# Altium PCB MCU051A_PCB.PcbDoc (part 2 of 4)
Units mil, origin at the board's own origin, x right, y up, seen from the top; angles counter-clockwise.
Board outline 4000 x 6000 mil, 6 copper layers (Top Layer, Signal Layer 1, Signal Layer 2, Signal Layer 3, Signal Layer 4, Bottom Layer), stack 60.4 mil thick; 193 components, 239 nets, 864 pads, 621 vias.
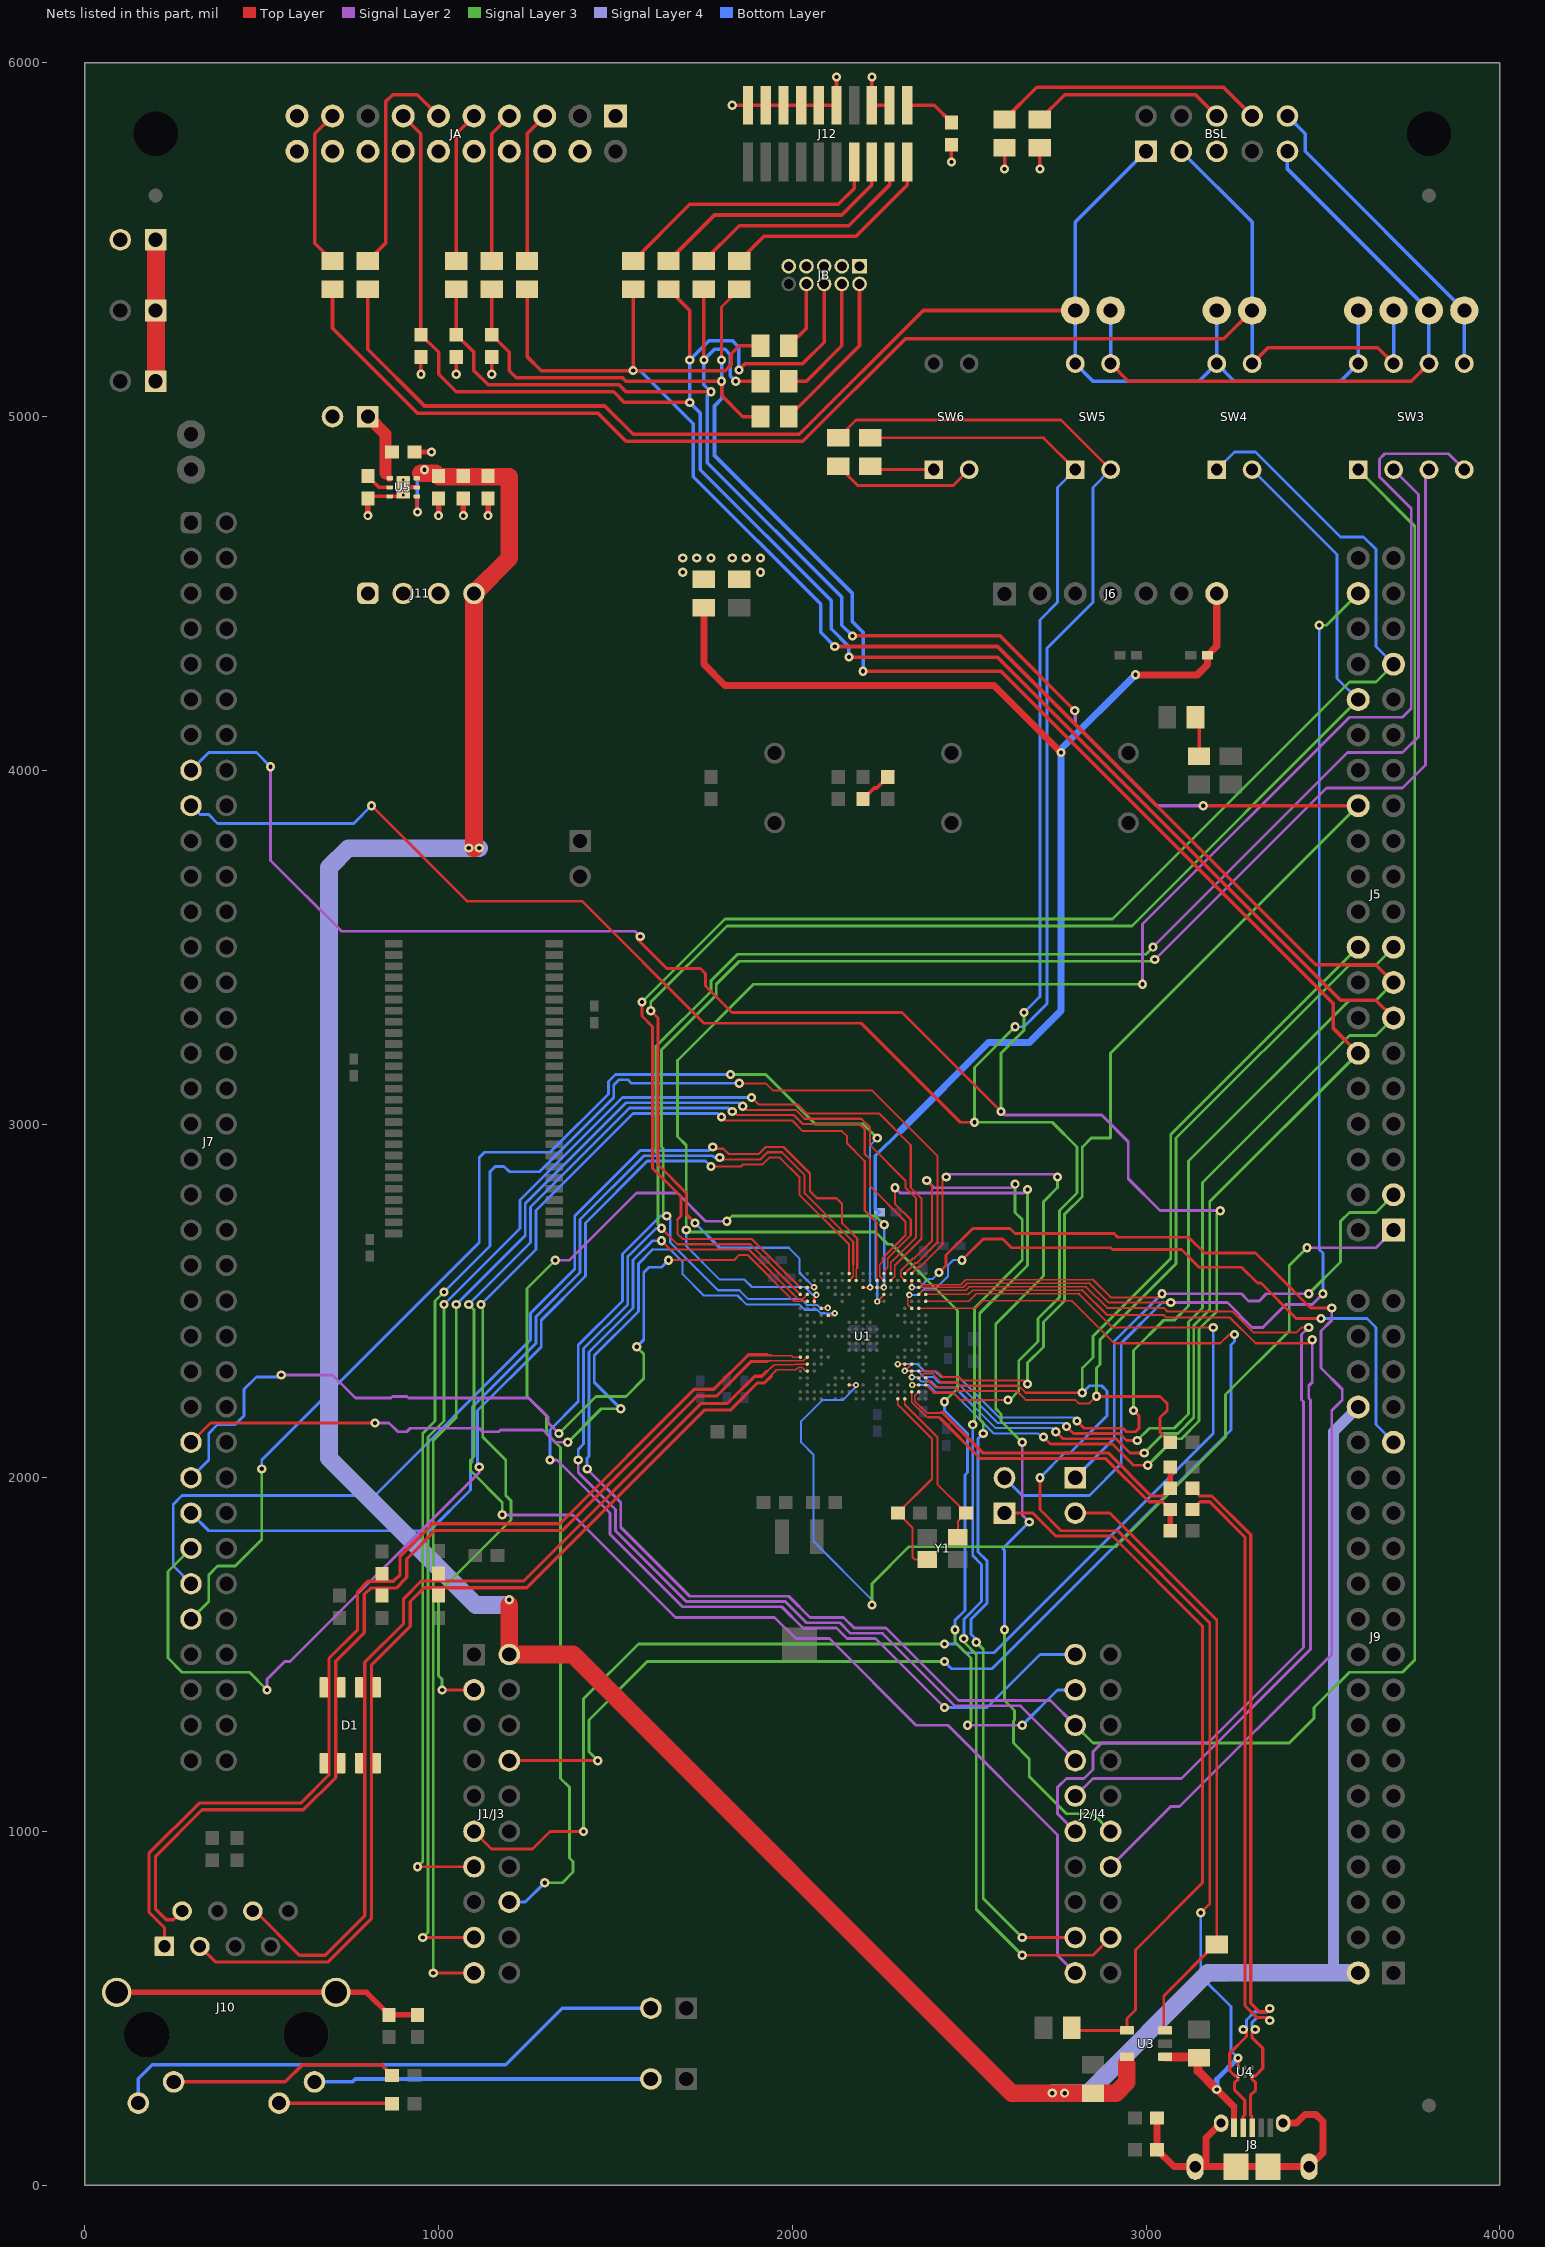
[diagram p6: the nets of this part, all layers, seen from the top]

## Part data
BSL: library part CMP-0075161-1, "Header(Shrouded), 2.54mm, 5x2, Gold, TH", Color=Gray, Manufacturer="Assman WSW", Supplier Part Number 1=AWHW-10G-0202-T-ND
C1 C2 C3 C14 C15 C16 C17 C19 C20 C21 C22 C23 C24 C25 C26 C30 C34: library part CMP-0006629-2, "CAP, CERM, 0.1 uF, 10 V, +/- 10%, X7R, 0402", Cap_Case=0402, Manufacturer=MuRata, Supplier Part Number 1=GRM155R71A104KA01D-ND, TempCo=X7R, Tolerance_%=10%, Value1=Unknown, Value2=10V, ValueDisplayed=0.1uF
C4 C8 C9 C12 C13 C36: library part CMP-0007378-5, "CAP, CERM, 0.1 uF, 16 V, +/- 10%, X7R, 0603", Cap_Case=0603, Manufacturer=MuRata, Supplier Part Number 1=490-1532-1-ND, TempCo=X7R, Tolerance_%=10%, Value1=Unknown, Value2=16V, ValueDisplayed=0.1uF
C5: library part CMP-0007724-2, "CAP, CERM, 0.1 uF, 16 V, +/- 10%, X7R, 0805", Cap_Case=0805, Manufacturer=Kemet, Supplier Part Number 1=399-1167-1-ND, TempCo=X7R, Tolerance_%=10%, Value1="0.064 ohm", Value2=16V, ValueDisplayed=0.1uF
C6 C7 C10 C11: library part CMP-0007178-4, "CAP, CERM, 12 pF, 50 V, +/- 5%, C0G/NP0, 0603", Cap_Case=0603, Manufacturer=MuRata, Supplier Part Number 1=490-1405-1-ND, TempCo=C0G/NP0, Tolerance_%=5%, Value1=Unknown, Value2=50V, ValueDisplayed=12pF
C18: library part CMP-0006746-5, "CAP, CERM, 4700 pF, 100 V, +/- 10%, X7R, 0603", Cap_Case=0603, Manufacturer=AVX, Supplier Part Number 1=478-1203-1-ND, TempCo=X7R, Tolerance_%=10%, Value1="0.136 ohm", Value2=100V, ValueDisplayed=4700pF
C27 C28: library part CMP-0007690-2, "CAP, CERM, 4.7 uF, 10 V, +/- 10%, X7R, 0805", Cap_Case=0805, Manufacturer="Wurth Elektronik", Supplier Part Number 1=710-885012207025, TempCo=X7R, Tolerance_%=10%, Value1=Unknown, Value2=10V, ValueDisplayed=4.7uF
C29 C33: library part CMP-0064947-2, "CAP, CERM, 1 uF, 6.3 V,+/- 10%, X7R, 0402", Cap_Case=0402, Manufacturer=MuRata, Supplier Part Number 1=490-10024-1-ND, TempCo=X7R, Tolerance_%=10%, Value1=Unknown, Value2=6.3V, ValueDisplayed=1uF
C31: library part CMP-0007445-4, "CAP, CERM, 0.22 uF, 50 V, +/- 10%, X7R, 0603", Cap_Case=0603, Manufacturer=MuRata, Supplier Part Number 1=490-12546-1-ND, TempCo=X7R, Tolerance_%=10%, Value1=Unknown, Value2=50V, ValueDisplayed=0.22uF
C32 C38: library part CMP-0007499-4, "CAP, CERM, 2.2 uF, 16 V, +/- 10%, X7R, 0603", Cap_Case=0603, Manufacturer=MuRata, Supplier Part Number 1=81-GRM188Z71C225KE3D, TempCo=X7R, Tolerance_%=10%, Value1=Unknown, Value2=16V, ValueDisplayed=2.2uF
C35: library part CMP-0007365-4, "CAP, CERM, 1 uF, 10 V, +/- 10%, X7R, 0603", Cap_Case=0603, Manufacturer=MuRata, Supplier Part Number 1=490-3899-1-ND, TempCo=X7R, Tolerance_%=10%, Value1="0.011 ohm", Value2=10V, ValueDisplayed=1uF
C37 C39: library part CMP-0007377-4, "CAP, CERM, 0.01 uF, 16 V, +/- 10%, X7R, 0603", Cap_Case=0603, Manufacturer=MuRata, Supplier Part Number 1=490-1525-1-ND, TempCo=X7R, Tolerance_%=10%, Value1=Unknown, Value2=16V, ValueDisplayed=0.01uF
D1: library part CMP-0082307-1, "Low Capacitance TVS Array, 2.8V, SOIC-8", Manufacturer=Bourns, Supplier Part Number 1=CDNBS08-SLVU2.8-4CT-ND
FID1 FID2 FID3 FID4 FID5 FID6: library part CMP-0077181-1, "Fiducial mark.  There is nothing to buy or mount.", Manufacturer=N/A
H1 H2: library part CMP-0003658-1, Manufacturer=Keystone, Supplier Part Number 1=36-1902B-ND
J1/J3: library part CMP-0003837-2, "Receptacle, 2.54mm, 10x2, Tin, TH", Alternate Manufacturer="Major League Electronics", Alternate PartNumber=CRD-081413-A-G, Manufacturer=Samtec, Supplier Part Number 1=SAM1204-10-ND
J2/J4: library part CMP-0078266-2, "Receptacle, 2.54mm, 10x2, Tin, TH", Alternate Manufacturer="Major League Electronics", Alternate PartNumber=CRD-081413-A-G, Manufacturer=Samtec, Supplier Part Number 1=SAM1204-10-ND
J5 J9: library part CMP-0075433-1, "Header, 100mil, 20x2, Gold, TH", Color=Black, Current_A=6.3A, Manufacturer=Samtec, Supplier Part Number 1=SAM1028-20-ND, Voltage_V=550V
J6: library part CMP-0075416-1, "Header, 100mil, 7x1, Gold, TH", Color=Black, Current_A=6.3A, Manufacturer=Samtec, Supplier Part Number 1=SAM1029-07-ND, Voltage_V=550V
J7: library part CMP-0080465-1, "Header, 2.54mm, 36x2, Gold, TH", Color=Black, Manufacturer=Samtec, Supplier Part Number 1=SAM1028-36-ND
J8: library part CMP-0075082-1, "Connector, Receptacle, Micro-USB Type AB, R/A, Bottom Mount SMT", Manufacturer="Hirose Electric Co. Ltd.", Supplier Part Number 1=H11494CT-ND
J10: library part CMP-0055856-1, "Connector, RJ45 with integrated magnetics, 1x1, Gold, R/A, TH", Manufacturer="Pulse Engineering", Supplier Part Number 1=553-1485-ND
J11: library part CMP-0078238-2, "Header, 2.54mm, 4x1, Tin, TH", Color=Black, Manufacturer=Samtec, Supplier Part Number 1=SAM1035-04-ND
J12: library part CMP-0075631-1, "Header (Shrouded), 1.27mm, 10x2, Tin, SMT", Color=Black, Current_A=3.3A, Manufacturer=Samtec, Supplier Part Number 1=SAM8803-ND
JA: library part CMP-0054842-1, "Header (shrouded), 100mil, 10x2,  Gold, TH", Manufacturer="TE Connectivity", Supplier Part Number 1=A33166-ND
JB: library part CMP-0075533-1, "Header, 1.27 mm, 5x2, Gold, TH", Color=Black, Manufacturer=Samtec, Supplier Part Number 1=FTSH-105-01-F-D-K-ND
JP1 JP2 JP3 JP4 JP5 JP6 JP7 JP8 JP9: library part CMP-0075500-1, "Header, 100mil, 2x1, Gold, TH", Manufacturer=Samtec, Supplier Part Number 1=HMTSW-102-07-G-S-240-ND
Logo1: library part CMP-0074838-1, "Texas Instrument Corporate Signature"
Logo2: library part CMP-0074844-1
Logo3: library part CMP-0074847-1, "FCC_disclaimer"
Logo4: library part CMP-0074769-1
MH1 MH2: library part CMP-0078424-2, "PCB Mounting Hole, No Pad", Manufacturer=Any, PartNumber=N/A
R1: library part CMP-0025925-3, "RES, 47 k, 5%, 0.1 W, 0603", Manufacturer="Yageo America", Power_W=100mW, Supplier Part Number 1=311-47KGRCT-ND, TempCo="100 ppm/C", Tolerance_%=5%, Value2=0.1W, Value_Code=47k0, ValueDisplayed=47k
R2: library part CMP-0025825-4, "RES, 51, 5%, 0.1 W, AEC-Q200 Grade 0, 0603", Manufacturer=Vishay-Dale, Power_W=100mW, Supplier Part Number 1=541-51GCT-ND, TempCo="200 ppm/C", Tolerance_%=5%, Value2=0.1W, Value_Code=51R0, ValueDisplayed=51
R3: library part CMP-0020445-3, "RES, 100, 5%, 0.125 W, AEC-Q200 Grade 0, 0805", Manufacturer=Vishay-Dale, Power_W=125mW, Supplier Part Number 1=541-100ACT-ND, TempCo="200 ppm/C", Tolerance_%=5%, Value2=0.125W, Value_Code=100R, ValueDisplayed=100
R4 R32 R33: library part CMP-0020446-3, "RES, 10 k, 5%, 0.125 W, AEC-Q200 Grade 0, 0805", Manufacturer=Vishay-Dale, Power_W=125mW, Supplier Part Number 1=541-10KACT-ND, TempCo="200 ppm/C", Tolerance_%=5%, Value2=0.125W, Value_Code=10k0, ValueDisplayed=10k
R5 R14: library part CMP-0025736-4, "RES, 1.0 M, 5%, 0.1 W, AEC-Q200 Grade 0, 0603", Manufacturer=Vishay-Dale, Power_W=100mW, Supplier Part Number 1=541-1.0MGCT-ND, TempCo="200 ppm/C", Tolerance_%=5%, Value2=0.1W, Value_Code=1M00, ValueDisplayed=1.0M
R6: library part CMP-0023154-3, "RES, 4.87 k, 1%, 0.1 W, 0603", Manufacturer="Yageo America", Power_W=100mW, Supplier Part Number 1=311-4.87KHRCT-ND, TempCo="200 ppm/C", Tolerance_%=1%, Value2=0.1W, Value_Code=4k87, ValueDisplayed=4.87k
R7 R15 R24 R25: library part CMP-0020803-2, "RES, 0, 5%, 0.125 W, 0805", Manufacturer="Yageo America", Power_W=125mW, Supplier Part Number 1=311-0.0ARCT-ND, TempCo="200 ppm/C", Tolerance_%=5%, Value2=0.125W, Value_Code=0000, ValueDisplayed=0
R8 R9 R12 R13: library part CMP-0023143-3, "RES, 49.9, 1%, 0.1 W, 0603", Manufacturer="Yageo America", Power_W=100mW, Supplier Part Number 1=311-49.9HRCT-ND, TempCo="200 ppm/C", Tolerance_%=1%, Value2=0.1W, Value_Code=49R9, ValueDisplayed=49.9
R10 R11: library part CMP-0020559-3, "RES, 4.7 k, 5%, 0.125 W, AEC-Q200 Grade 0, 0805", Manufacturer=Vishay-Dale, Power_W=125mW, Supplier Part Number 1=541-4.7KACT-ND, TempCo="200 ppm/C", Tolerance_%=5%, Value2=0.125W, Value_Code=4k70, ValueDisplayed=4.7k
R16 R23: library part CMP-0025912-3, "RES, 330, 5%, 0.1 W, 0603", Manufacturer="Yageo America", Power_W=100mW, Supplier Part Number 1=311-330GRCT-ND, TempCo="100 ppm/C", Tolerance_%=5%, Value2=0.1W, Value_Code=330R, ValueDisplayed=330
R17 R18 R19 R20 R21 R22 R34 R38 R40 R41: library part CMP-0020509-3, "RES, 27, 5%, 0.125 W, AEC-Q200 Grade 0, 0805", Manufacturer=Vishay-Dale, Power_W=125mW, Supplier Part Number 1=541-27ACT-ND, TempCo="200 ppm/C", Tolerance_%=5%, Value2=0.125W, Value_Code=27R0, ValueDisplayed=27
R26 R27 R28 R29: library part CMP-0025697-4, "RES, 0, 5%, 0.1 W, AEC-Q200 Grade 0, 0603", Manufacturer=Vishay-Dale, Power_W=100mW, Supplier Part Number 1=541-0.0GCT-ND, TempCo="200 ppm/C", Tolerance_%=5%, Value2=0.1W, Value_Code=0000, ValueDisplayed=0
R30: library part CMP-0025700-4, "RES, 100, 5%, 0.1 W, AEC-Q200 Grade 0, 0603", Manufacturer=Vishay-Dale, Power_W=100mW, Supplier Part Number 1=541-100GCT-ND, TempCo="200 ppm/C", Tolerance_%=5%, Value2=0.1W, Value_Code=100R, ValueDisplayed=100
R31: library part CMP-0025913-3, "RES, 33 k, 5%, 0.1 W, 0603", Manufacturer="Yageo America", Power_W=100mW, Supplier Part Number 1=311-33KGRCT-ND, TempCo="100 ppm/C", Tolerance_%=5%, Value2=0.1W, Value_Code=33k0, ValueDisplayed=33k
R35 R36 R37: library part CMP-0025945-3, "RES, 10 k, 5%, 0.1 W, 0603", Manufacturer="Samsung Electro-Mechanics", Power_W=100mW, Supplier Part Number 1=1276-5086-1-ND, TempCo="100 ppm/C", Tolerance_%=5%, Value2=0.1W, Value_Code=10k0, ValueDisplayed=10k
R39: library part CMP-0022736-2, "RES, 100, 1%, 0.1 W, 0603", Manufacturer="Yageo America", Power_W=100mW, Supplier Part Number 1=311-100HRCT-ND, TempCo="200 ppm/C", Tolerance_%=1%, Value2=0.1W, Value_Code=100R, ValueDisplayed=100
R42 R43: library part CMP-0020442-3, "RES, 0, 5%, 0.125 W, AEC-Q200 Grade 0, 0805", Manufacturer=Vishay-Dale, Power_W=125mW, Supplier Part Number 1=541-0.0ACT-ND, TempCo="200 ppm/C", Tolerance_%=5%, Value2=0.125W, Value_Code=0000, ValueDisplayed=0
SH-J7-1 SH-J7-2 SH-J7-3 SH-J7-4 SH-J7-5 SH-J7-6 SH-J7-7 SH-J7-8 SH-J7-9 SH-J7-10 SH-J7-11 SH-J7-12 SH-J7-13 SH-J7-14 SH-J7-15 SH-J7-16 SH-J7-17 SH-J7-18 SH-J7-19 SH-J7-20 SH-J7-21 SH-J7-22 SH-J7-23 SH-J7-24 SH-J7-25 SH-J7-26 SH-J7-27 SH-J7-28 SH-J7-29 SH-J7-30 SH-J7-31 SH-J7-32 SH-J7-33 SH-J7-34 SH-J7-35 SH-J7-36 SH-JP1 SH-JP2 SH-JP3 SH-JP4 SH-JP5 SH-JP6 SH-JP7 SH-JP8 SH-JP9: library part CMP-0003623-1, "Shunt, 100mil, Gold plated, Black", Alternate Manufacturer=3M, Alternate PartNumber=969102-0000-DA, Manufacturer=Samtec, Supplier Part Number 1=SNT-100-BK-G-ND
SW1 SW2 SW7: library part CMP-0074594-1, "Switch, SPST-NO, Off-Mom, 0.02 A, 15 VDC, TH", CurrentRating_mA=20A, Manufacturer=Panasonic, Supplier Part Number 1=P8070SCT-ND
SW3: library part CMP-0002271-1, "Switch, 4PST, Slide, Off-On, 1 Pos, 0.15A, 30V, TH", CurrentRating_mA=150A, Manufacturer=Grayhill, Supplier Part Number 1=GH7198-ND
SW4 SW5 SW6: library part CMP-0002270-1, "Switch, DPST, Slide, Off-On, 1 Pos, 0.15A, 30V, TH", CurrentRating_mA=150A, Manufacturer=Grayhill, Supplier Part Number 1=GH7727-ND
TP1 TP2 TP3 TP4 TP5 TP6 TP7 TP8 TP9 TP10: library part CMP-0055138-1, "Test Point, Miniature, Black, TH", Color=Black, Manufacturer=Keystone, Supplier Part Number 1=36-5001-ND
U1: library part CMP-0077957-1, "MSP432E411YTZAD, ZAD0212A (NFBGA-212)", Alternate Manufacturer="Texas Instruments", Alternate PartNumber=MSP432E411YTZADR
U2: library part CMP-0004972-1, "32Mx16 512Mb SDRAM, TSOP-2_54", Manufacturer="Integrated Silicon Solution Inc.", Supplier Part Number 1=706-1450-5-ND
U3: library part CMP-0074276-1, "Single, Current-Limited, Power-Distribution Switch, DBV0005A (SOT-23-5)", Alternate Manufacturer="Texas Instruments", Alternate PartNumber=TPS2051BDBVT
U4: library part CMP-0043122-2, "USB ESD Solution with Power Clamp, 4 Channels, -40 to +85 degC, 6-pin SON (DRY), Green (RoHS & no Sb/Br)", Breakdown Voltage(Min)(V)=6, IO Capacitance(Typ)(pF)=0.8, IO Leakage Current(nA)=10, Manufacturer="Texas Instruments"
U5: library part CMP-0036330-5, "Single Output High PSRR LDO, 500 mA, Fixed 3.3 V Output, 2.7 to 6.5 V Input, with Low IQ, 6-pin SON (DRV), -40 to 125 degC, Green (RoHS & no Sb/Br)", Manufacturer="Texas Instruments"
Y1: library part CMP-0004652-3, "Crystal, 25 MHz, 8pF, SMD", Frequency_Fixed=25MHz, Frequency Stability=+/-20ppm, Manufacturer=Fox, Supplier Part Number 1=631-1478-1-ND
Y2: library part CMP-0004653-5, "Crystal, 32.768 kHz,  SMD", Frequency_Fixed=32.768kHz, Frequency Stability=+/-20ppm, Manufacturer="Citizen FineDevice", Supplier Part Number 1=695-CMR200T32.7KY-U
ZZ2: library part CMP-0077236-1
ZZ3: library part CMP-0077237-1
ZZ4 ZZ5 ZZ6: library part CMP-0077238-1

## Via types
v1: diameter 26, hole 12, Top Layer to Bottom Layer, tented both sides, 517 vias
v2: diameter 18, hole 8, Top Layer to Bottom Layer, tented both sides, 94 vias
v3: diameter 26, hole 12, Top Layer to Bottom Layer, 7 vias
v4: diameter 19.68, hole 7.87, Top Layer to Bottom Layer, 2 vias
v5: diameter 18, hole 8, Top Layer to Bottom Layer, 1 vias

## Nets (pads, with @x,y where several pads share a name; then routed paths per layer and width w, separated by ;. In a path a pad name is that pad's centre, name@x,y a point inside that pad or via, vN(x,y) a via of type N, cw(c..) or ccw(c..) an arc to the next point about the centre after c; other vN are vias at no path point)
3V3: J11.1 JA.1 JA.19 JB.1 JP1.2 JP8.2 R7.1 R15.1 R35.1 R36.1 R37.1 R39.1 | length 314
  Top Layer w10: v1(950,5120) R37.1@950,5168.5 ; v1(1050,5120) R36.1@1050,5168.5 ; v1(1150,5120) R35.1@1150,5168.5 ; v1(2450,5720) R39.1@2450,5768.5 ; v1(2600,5700) R7.1@2600,5760 ; v1(2700,5700) R15.1@2700,5760
5V0: C28.1 C35.1 C36.1 C37.1 J1/J3.21 J9.2 J9.34 J11.4 U3.5 U5.4 U5.6 | length 9432.4
  Top Layer w10: U5.4@938.39,4774.41 938.39,4731.61 v1(940,4730)
  Top Layer w25: 2945.87,342.5 U3.5@2945.87,362.6
  Top Layer w50: 950,4840 991.5,4840 C37.1@1000,4831.5 1001.5,4830 1200,4830 1200,4600 J11.4@1100,4500 1100,3780 ; 1200,1640 J1/J3.21@1200,1500 1380,1500 2620,260 v1(2735,260) C28.1@2850,260 2915,260 2945.87,290.87 2945.87,342.5
  Signal Layer 4 w30: 3530,600 3530,2130 J9.34@3600,2200
  Signal Layer 4 w50: v1(1115,3780) 745,3780 690,3725 690,2055 1105,1640 1195,1640 ; v1(2735,260) 2835,260 3175,600 3530,600 J9.2@3600,600
  Bottom Layer w10: v1(940,4730) 940,4830 v1(960,4850)
  other v1: 2770,260 1200,1655 1085,3780
AVSS: C29.1 C30.1 J6.7 R43.2 U1.G4 | length 3884.4
  Top Layer w6: v2(2240,2498) 2259.06,2517.06 U1.G4@2259.06,2518.11
  Top Layer w20: R43.2@1750,4460 1750,4300 1810,4240 2570,4240 v1(2760,4050) ; v1(2970,4270) 3030,4270 3145,4270 3173.62,4298.62 C29.1@3173.62,4325 3200,4351.38 J6.7@3200,4500
  Bottom Layer w6: v2(2240,2498) 2240,2560.54 2235.27,2565.27 2235.27,2738.89 C30.1@2246.38,2750
  Bottom Layer w10: C30.1@2246.38,2750 2235,2761.38 2235,2910 2305,2980
  Bottom Layer w20: 2305,2980 2555,3230 2670,3230 2760,3320 v1(2760,4050) 2760,4060 v1(2970,4270)
BSLCLK: BSL.9 SW3.6 SW5.4 TP6.1 TP9.1 | length 1857.1
  Top Layer w10: SW5.4@2900,5150 2950,5100 3750,5100 SW3.6@3800,5150
  Bottom Layer w10: SW5.4@2900,5150 TP6.1@2900,5300 ; BSL.9@3400,5750 3400,5700 TP9.1@3800,5300 SW3.6@3800,5150
BSLRX: BSL.3 R25.2 SW3.4 SW4.4 TP4.1 TP8.1 | length 4265.8
  Top Layer w10: R25.2@700,5360 700,5250 940,5010 1450,5010 1530,4930 2030,4930 2320,5220 3220,5220 TP4.1@3300,5300 ; SW4.4@3300,5150 3344.88,5194.88 3655.12,5194.88 SW3.4@3700,5150
  Bottom Layer w10: BSL.3@3100,5750 3300,5550 TP4.1@3300,5300 SW4.4@3300,5150 ; SW3.4@3700,5150 TP8.1@3700,5300
BSLSDA: BSL.1 R24.2 SW3.2 SW4.2 SW5.2 TP3.1 TP5.1 TP7.1 | length 4280.1
  Top Layer w10: R24.2@800,5360 800,5190 960,5030 1470,5030 1550,4950 2020,4950 2370,5300 TP5.1@2800,5300
  Bottom Layer w10: BSL.1@3000,5750 2800,5550 TP5.1@2800,5300 SW5.2@2800,5150 2850,5100 3150,5100 SW4.2@3200,5150 ; TP3.1@3200,5300 SW4.2@3200,5150 ; TP7.1@3600,5300 SW3.2@3600,5150 3550,5100 3250,5100 SW4.2@3200,5150
BSLSTE: BSL.10 SW3.8 TP10.1 | length 907.1
  Bottom Layer w10: BSL.10@3400,5850 3450,5800 3450,5750 TP10.1@3900,5300 SW3.8@3900,5150
D_N: R26.2 R27.1 U1.B18 | length 933.3
  Top Layer w4: U1.B18@2357.48,2242.52 2346.56,2231.6 2346.56,2216.44 2380,2183 2385,2183
  Top Layer w6: 2385,2183 2419,2183 2420,2184
  Top Layer w8: 2420,2184 2425.63,2184
  Top Layer w9: 2425.63,2183 2538.63,2070 2893,2070 3015,1948 3046.5,1948 R27.1@3068.5,1970
  Top Layer w15: R27.1@3068.5,1970 R26.2@3068.5,2030
D_P: R28.2 R29.1 U1.C18 | length 945.8
  Top Layer w4: U1.C18@2337.8,2242.52 2337.8,2212.93 2379.73,2171 2385.69,2171
  Top Layer w6: 2385.69,2171 2415,2171 2418,2168
  Top Layer w9: 2418,2168 2532,2054 2886.37,2054 3008.37,1932 3046.5,1932 R29.1@3068.5,1910
  Top Layer w15: R28.2@3068.5,1850 R29.1@3068.5,1910
EN0RXI_N: D1.2 D1.7 J10.6 R12.1 U1.V14 | length 2775.2
  Top Layer w4: 1940.69,2311.9 1942.1,2311.9 1948.83,2318.63 2004.65,2318.63 2007.28,2321.26 U1.V14@2042.52,2321.26 U1.V14@2040.52,2319.26
  Top Layer w6: 1927.27,2300.61 1929.39,2300.61 1940.69,2311.9
  Top Layer w9: J10.6@475,774.8 481.47,774.8 606.28,650 680,650 791,761 791,1477.87 901,1587.87 901,1657.87 951.13,1708 1241.13,1708 1743.13,2210 1816.81,2210 1893.48,2286.67 1913.33,2286.67 1927.27,2300.61
EN0RXI_P: D1.1 D1.8 J10.3 R13.1 U1.V15 | length 2901.3
  Top Layer w4: 1952,2300.59 1952,2302 1954.63,2304.63 2010.44,2304.63 2018.31,2312.5 2027.36,2312.5 2033.76,2306.1 2033.76,2303.42 2035.6,2301.57 U1.V15@2042.52,2301.57
  Top Layer w6: 1940.71,2287.17 1940.71,2289.29 1952,2300.59
  Top Layer w9: J10.3@325,674.8 368.8,631 687.87,631 810,753.13 810,1470 920,1580 920,1650 959,1689 1249,1689 1751,2191 1824.68,2191 1901.35,2267.67 1921.2,2267.67 1940.71,2287.17
EN0TXO_N: D1.3 D1.6 J10.2 R9.1 U1.V13 | length 2962
  Top Layer w4: 1939,2330.32 1940,2331.32 1992.04,2331.32 1993.33,2330.02 2031.6,2330.02 U1.V13@2042.52,2340.94
  Top Layer w6: 1928.5,2328.82 1930,2330.32 1939,2330.32
  Top Layer w9: J10.2@275,774.8 250.2,750 230,750 200,780 200,930 331,1061 617.87,1061 709,1152.13 709,1481.13 790,1562.13 790,1670 808,1688 879.87,1688 910,1718.13 910,1770 991,1851 1351,1851 1731,2231 1786.16,2231 1883.97,2328.82 1928.5,2328.82
EN0TXO_P: D1.4 D1.5 J10.1 R8.1 U1.W13 | length 2996.2
  Top Layer w4: 1939,2346.32 1940,2345.32 1997.84,2345.32 2001.94,2341.21 ; 2001.94,2340.94 U1.W13@2022.83,2340.94
  Top Layer w6: 1928.5,2347.82 1930,2346.32 1939,2346.32
  Top Layer w9: J10.1@225,674.8 225,728.13 181,772.13 181,937.87 323.13,1080 610,1080 690,1160 690,1489 771,1570 771,1677.87 800.13,1707 872,1707 891,1726 891,1777.87 983.13,1870 1343.13,1870 1723.13,2250 1778.29,2250 1876.1,2347.82 1928.5,2347.82
GND: BSL.5 C35.2 C36.2 C37.2 C38.2 C39.2 J11.2 J11.3 J12.3 J12.5 J12.9 J12.11 J12.13 J12.15 J12.17 J12.19 JA.4 JA.6 JA.8 JA.10 JA.12 JA.14 JA.16 JA.18 JA.20 JB.3 JB.5 JB.7 JB.9 R42.1 R43.1 U5.3 U5.5 U5.7@900,4800 | length 863.9
  Top Layer w10: C39.2@805.91,4774.41 U5.3@861.61,4774.41 U5.7@884.25,4774.41 ; v3(1830.12,5880.12) J12.19@1875,5880.12 J12.17@1925,5880.12 J12.15@1975,5880.12 J12.13@2025,5880.12 J12.11@2075,5880.12 J12.9@2125,5880.12 v3(2125,5960) ; v3(2225,5960) J12.5@2225,5880.12 J12.3@2275,5880.12
  Top Layer w12: U5.7@900,4800 U5.5@938.39,4800
  Top Layer w15: v1(800,4720) C39.2@800,4768.5 ; C38.2@931.5,4900 v1(980,4900) ; v1(1000,4720) C37.2@1000,4768.5 ; v1(1070,4720) C36.2@1070,4768.5 ; v1(1140,4720) C35.2@1140,4768.5
  other v1: 1690,4560 1910,4560 1690,4600 1730,4600 1770,4600 1830,4600 1870,4600 1910,4600
  other v4: 900,4778.35 900,4821.65
HIBn: J5.1 U1.M17 | length 2950.1
  Top Layer w6: U1.M17@2160.63,2262.2 v2@2179.8,2262.2
  Signal Layer 2 w8: v1(3455,2650) 3650,2650 J5.1@3700,2700
  Signal Layer 3 w8: v1(2225,1640) 2225,1700 2330,1805 2915,1805 3225,2115 3225,2235 3405,2415 3405,2600 v1(3455,2650)
  Bottom Layer w6: v2(2180,2262) 2180,2257 2142.25,2219.25 2084.25,2219.25 2025,2160 2025,2100 2060,2065 2060,1820 2225,1655 v1(2225,1640)
NetBSL_6: BSL.6 R15.2 | length 553.8
  Top Layer w10: R15.2@2700,5840 2770,5910 3140,5910 BSL.6@3200,5850
NetBSL_8: BSL.8 R7.2 | length 771.2
  Top Layer w10: R7.2@2600,5840 2690.91,5930.91 3219.09,5930.91 BSL.8@3300,5850
NetC5_2: C5.2 R3.2 | length 114.1
  Top Layer w10: C5.2@3140,4150 3150,4140 R3.2@3150,4040
NetC18_1: C18.1 J10.13 J10.14 R14.2 | length 876.3
  Top Layer w15: J10.13@89.96,544.88 J10.14@710.04,544.88 796.61,544.88 C18.1@860,481.5 R14.2@940,481.5
NetC31_1: C31.1 J8.6 J8.7 J8.8 J8.9 J8.10 J8.11 R31.2 | length 954.8
  Top Layer w20: R31.2@3031.5,190 C31.1@3031.5,100 3079.33,52.17 J8.8@3139.07,52.17 3170,52.17 ; J8.10@3212.4,175.2 3170,132.8 3170,52.17 ; J8.11@3387.6,175.2 3425.2,175.2 3450,200 3480,200 3500,180 3500,91.24 J8.9@3460.93,52.17 J8.7@3345.28,52.17 J8.6@3254.72,52.17 3170,52.17
NetC38_1: C38.1 JP8.1 U5.1 | length 183.5
  Top Layer w20: U5.1@861.61,4825.59 U5.1@861.61,4828.39
  Top Layer w35: JP8.1@800,5000 850,4950 850,4840
NetC39_1: C39.1 U5.2 | length 74.7
  Top Layer w10: C39.1@800,4831.5 831.5,4800 U5.2@861.61,4800
NetJ10_9: J10.9 JP6.2 | length 1600.5
  Bottom Layer w10: J10.9@150.98,231.89 150.98,300.98 190,340 1190,340 1350,500 JP6.2@1600,500
NetJ10_10: J10.10 R16.2 | length 649.9
  Top Layer w10: J10.10@250.98,291.73 566.73,291.73 615,340 838.5,340 R16.2@868.5,310
NetJ10_11: J10.11 R23.2 | length 320.3
  Top Layer w10: J10.11@549.02,231.89 866.61,231.89 R23.2@868.5,230
NetJ10_12: J10.12 JP7.2 | length 954.4
  Bottom Layer w10: J10.12@649.02,291.73 756.73,291.73 765,300 JP7.2@1600,300
NetJ12_1: J12.1 R39.2 | length 145.1
  Top Layer w10: J12.1@2325,5880.12 2401.38,5880.12 R39.2@2450,5831.5
NetJ12_2: J12.2 R34.1 | length 628.9
  Top Layer w10: R34.1@1850,5440 1920,5510 2180,5510 2325,5655 J12.2@2325,5719.88
NetJ12_4: J12.4 R38.1 | length 678.9
  Top Layer w10: R38.1@1750,5440 1850,5540 2160,5540 2275,5655 J12.4@2275,5719.88
NetJ12_6: J12.6 R40.1 | length 728.9
  Top Layer w10: R40.1@1650,5440 1780,5570 2140,5570 2225,5655 J12.6@2225,5719.88
NetJ12_8: J12.8 R41.1 | length 784.8
  Top Layer w10: R41.1@1550,5440 1710,5600 2130,5600 2175,5645 J12.8@2175,5719.88
NetJA_5: JA.5 R19.1 | length 430.7
  Top Layer w10: R19.1@1250,5440 1250,5800 JA.5@1300,5850
NetJA_7: JA.7 R18.1 | length 430.7
  Top Layer w10: R18.1@1150,5440 1150,5800 JA.7@1200,5850
NetJA_9: JA.9 R17.1 | length 430.7
  Top Layer w10: R17.1@1050,5440 1050,5800 JA.9@1100,5850
NetJA_11: JA.11 R24.1 | length 653.8
  Top Layer w10: R24.1@800,5440 850,5490 850,5890 870,5910 940,5910 JA.11@1000,5850
NetJA_17: JA.17 R25.1 | length 451.4
  Top Layer w10: R25.1@700,5440 650,5490 650,5800 JA.17@700,5850
NetJB_2: JB.2 R21.2 | length 457.8
  Top Layer w10: R21.2@1990,5000 2190,5200 JB.2@2190,5375
NetJB_4: JB.4 R20.2 | length 366.4
  Top Layer w10: R20.2@1990,5100 2040,5100 2140,5200 JB.4@2140,5375
NetJB_8: JB.8 R22.2 | length 195.7
  Top Layer w10: R22.2@1990,5200 2040,5250 JB.8@2040,5375
NetJP1_1: JP1.1 JP2.1 JP3.1 | length 393
  Top Layer w50: JP2.1@201,5101 JP1.1@201,5494
NetJP4_1: JP4.1 R33.2 U3.4 | length 2067.1
  Top Layer w8: JP4.1@2600,1900 2680,1900 2745,1835 2905,1835 3160,1580 3160,855 2970,665 2970,495 2945.87,470.87 U3.4@2945.87,437.4 R33.2@2802.6,437.4
NetJP5_2: JP5.2 R32.1 U3.3 | length 1743.4
  Top Layer w8: JP5.2@2800,1900 2897.5,1900 3200,1597.5 3200,685 3050,535 U3.3@3050,441.54
NetR2_2: R2.2 R5.2 | length 96.1
  Top Layer w10: R2.2@2200,3918.5 2231.5,3950 2238.5,3950 R5.2@2270,3981.5
NetR10_2: R10.2 SW6.1 | length 184.1
  Top Layer w8: R10.2@2220,4860 2230,4850 SW6.1@2400,4850
NetR11_2: R11.2 SW6.3 | length 411.3
  Top Layer w8: R11.2@2130,4860 2184.88,4805.12 2455.12,4805.12 SW6.3@2500,4850
OSC0: C6.2 U1.E19 Y1.1 | length 589.4
  Top Layer w4: U1.E19@2298.43,2222.83 2298.43,2206.57 2315,2190
  Top Layer w6: 2315,2190 2395,2110 2395,1996.5 C6.2@2298.5,1900 2340,1858.5 2340,1775 2346.5,1768.5 Y1.1@2381.69,1768.5
OSC1: C7.2 U1.D19 Y1.3 | length 472.8
  Top Layer w4: 2318.11,2206.89 U1.D19@2318.11,2222.83
  Top Layer w6: 2318.11,2206.89 2410,2115 2410,1981.5 C7.2@2491.5,1900 2468.31,1876.81 Y1.3@2468.31,1831.5
OTGD_N: J8.2 R27.2 U4.1 | length 2049.4
  Top Layer w9: R27.2@3131.5,1970 3153.5,1948 3186.63,1948 3296,1838.63 3296,514 3320,490 3343,490 v3@3350,497 ; 3236.81,323.19 3236.81,372.81 3284,420 3284,433 v3@3277,440 ; 3238.81,321.19 3250.83,309.17 U4.1@3260.31,309.17 3260.31,299.33 3250,289.02 3250,269.2 3279.2,240 3279.2,198.27 3274.41,193.48 J8.2@3274.41,162.4
  Bottom Layer w9: v3@3277,440 3284,447 3284,466.63 3307.37,490 3343,490 v3@3350,497
  other v3: 3275,440 3350,499
OTGD_P: J8.3 R29.2 U4.3 | length 2014.8
  Top Layer w9: R29.2@3131.5,1910 3153.5,1932 3180,1932 3280,1832 3280,507.37 3313.37,474 3343,474 v3@3350,467 ; J8.3@3300,162.4 3300,193.48 3295.2,198.27 3295.2,253.7 3310,268.5 3310,289.14 3299.68,299.45 U4.3@3299.68,308.19 3308.19,308.19 3330,330 3330,386.5 3300,416.5 3300,433 v3@3307,440
  Bottom Layer w9: v3@3307,440 3300,447 3300,460 3314,474 3343,474 v3@3350,467
  other v3: 3309,440 3350,465
PA0: J5.32 SW4.3 U1.V3 | length 4259.3
  Top Layer w6: U1.V3@2042.52,2537.8 v2@2061.2,2537.8
  Top Layer w8: v1(1600,3320) 1620,3300 1620,2885 1700,2805 1700,2745 v1(1725,2720)
  Signal Layer 3 w8: v1(1600,3320) 1600,3345 1815,3560 2960,3560 J5.32@3600,4200
  Bottom Layer w6: 1990,2650 2020,2620 2020,2580 v2(2061.7,2538.3)
  Bottom Layer w8: v1(1725,2720) 1795,2650 1990,2650 ; SW4.3@3300,4850 3540,4610 3540,4260 J5.32@3600,4200
PA1: J5.33 SW4.1 U1.W3 | length 4566.5
  Top Layer w6: 1675,2730 1675,2690 1690,2675 1885.63,2675 U1.W3@2022.83,2537.8
  Top Layer w8: v1(1575,3345) 1575,3305 1605,3275 1605,2875 1685,2795 1685,2740 1675,2730
  Signal Layer 3 w8: v1(1575,3345) 1810,3580 2905,3580 3575,4250 3650,4250 J5.33@3700,4300
  Bottom Layer w8: SW4.1@3200,4850 3250,4900 3310,4900 3550,4660 3615,4660 3650,4625 3650,4350 J5.33@3700,4300
PA2: J2/J4.40 SW3.5 U1.T6 | length 7154.9
  Top Layer w4: v2@2098.74,2478.74 v2(2100,2480)
  Top Layer w6: U1.T6@2081.89,2478.74 v2@2098.74,2478.74
  Signal Layer 2 w8: v1(1315,2050) 1335,2050 1485,1900 1485,1840 1690,1635 1970,1635 2030,1575 2125,1575 2155,1545 2235,1545 v1(2430,1350) ; v1(3025,3465) 3510,3950 3725,3950 3790,4015 3790,4840 SW3.5@3800,4850
  Signal Layer 3 w8: v1(1645,2740) 1635,2750 1635,2930 1630,2935 1630,3210 1785,3365 1785,3395 1850,3460 3020,3460 v1(3025,3465)
  Bottom Layer w6: v1(1645,2740) 1655,2730 1655,2665 1790,2530 1850,2530 1875,2505 2025,2505 2042,2488 2071.37,2488 2079.37,2480 v2(2100,2480)
  Bottom Layer w8: v1(1315,2050) 1315,2135 1395,2215 1395,2375 1520,2500 1520,2632.5 1627.5,2740 v1(1645,2740) ; v1(2430,1350) 2550,1350 2700,1500 J2/J4.40@2800,1500
PA3: J2/J4.39 SW3.7 U1.U5 | length 7041.3
  Top Layer w6: 2062.2,2492.88 U1.U5@2062.2,2498.43 2062.2,2511.2 v2(2068,2517)
  Signal Layer 2 w8: v1(2495,1300) v1(2650,1300) ; v1(2990,3395) 2990,3565 3575,4150 3725,4150 3750,4175 3750,4740 3660,4830 3660,4880 3675,4895 3855,4895 SW3.7@3900,4850
  Signal Layer 3 w8: v1(2430,2215) 2467.5,2252.5 2467.5,2472.5 2280,2660 2270,2660 2235,2695 1705,2695 v1(1700,2700) 1700,2940 1675,2965 1675,3180 1890,3395 v1(2990,3395) ; v1(2460,1570) 2460,1535 2505,1490 2505,1310 v1(2495,1300)
  Bottom Layer w6: v1(1700,2700) 1700,2655 1795,2560 1865,2560 1886,2539 2035,2539 2057,2517 v2(2068,2517)
  Bottom Layer w8: v1(2430,2215) 2430,2190 2495,2125 2495,2015 2488,2008 2488,1625 2460,1597 v1(2460,1570) ; v1(2650,1300) 2750,1400 J2/J4.39@2800,1400
PA4: J2/J4.38 SW3.1 U1.V4 | length 7480
  Top Layer w4: 2001.43,2520 2015,2506.43 2030.83,2506.43 U1.V4@2042.52,2518.11
  Top Layer w6: v1(1630,2670) 1655,2645 1876.43,2645 2001.43,2520
  Signal Layer 2 w8: v1(1420,2025) 1515,1930 1515,1860 1710,1665 1990,1665 2050,1605 2145,1605 2175,1575 2265,1575 2470,1370 2730,1370 J2/J4.38@2800,1300
  Signal Layer 3 w8: J2/J4.38@2800,1300 2850,1250 3405,1250 3475,1320 3475,1350 3575,1450 3725,1450 3760,1485 3760,4690 SW3.1@3600,4850
  Bottom Layer w8: v1(1420,2025) 1420,2055 1425,2060 1425,2355 1550,2480 1550,2615 1605,2670 v1(1630,2670)
PA5: J2/J4.37 SW3.3 U1.W4 | length 6884.3
  Top Layer w6: v1(1630,2705) 1675,2660 1880.95,2660 U1.W4@2022.83,2518.11
  Signal Layer 2 w8: v1(1395,2050) 1395,2015 1500,1910 1500,1850 1700,1650 1980,1650 2040.24,1589.76 2135.24,1589.76 2165,1560 2255,1560 2460,1355 2645,1355 J2/J4.37@2800,1200 ; v1(3020,3500) 3570,4050 3725,4050 3770,4095 3770,4780 SW3.3@3700,4850
  Signal Layer 3 w8: v1(1630,2705) 1620,2715 1620,2915 1615,2920 1615,3220 1770,3375 1770,3405 1845,3480 3000,3480 v1(3020,3500)
  Bottom Layer w8: v1(1395,2050) 1395,2080 1410,2095 1410,2365 1535,2490 1535,2625 1615,2705 v1(1630,2705)
PA6: J7.55 U1.V5 | length 2487.8
  Top Layer w4: 2000,2503.43 2005,2498.43 U1.V5@2042.52,2498.43
  Top Layer w6: v1(1650,2615) 1835,2615 1850,2630 1873.43,2630 2000,2503.43
  Signal Layer 2 w8: v1(555,2290) 700,2290 765,2225 865,2225 870,2230 910,2230 915,2225 1255,2225 1310,2170 1310,2155 v1(1340,2125)
  Signal Layer 3 w8: v1(1340,2125) 1445,2230 1530,2230 1580,2280 1580,2350 v1(1560,2370)
  Bottom Layer w8: J7.55@300,2000 350,2050 350,2125 375,2150 425,2150 450,2175 450,2250 485,2285 550,2285 v1(555,2290) ; v1(1560,2370) 1580,2390 1580,2580 1595,2595 1630,2595 v1(1650,2615)
PA7: J7.53 U1.R7 | length 2493.5
  Top Layer w6: U1.R7@2101.57,2459.06 2114.06,2459.06 v2(2120,2465)
  Top Layer w8: J7.53@300,2100 355,2155 v1(820,2155)
  Signal Layer 2 w8: v1(820,2155) 860,2155 885,2130 910,2130 920,2140 1115,2140 1125,2130 1170,2130 1175,2135 1295,2135 1330,2100 v1(1365,2100)
  Signal Layer 3 w8: v1(1365,2100) 1460,2195 v1(1515,2195)
  Bottom Layer w6: 1605,2645 1655,2645 1690,2610 1690,2575 1750,2515 1845,2515 1870,2490 2020,2490 2035,2475 2070.23,2475 2080.23,2465 2092.37,2465 2093.37,2464 2119,2464 v2(2120,2465)
  Bottom Layer w8: v1(1515,2195) 1440,2270 1440,2345 1565,2470 1565,2605 1605,2645
PB0: J5.17 R30.1 U1.A16 | length 2521.1
  Top Layer w6: U1.A16@2377.17,2281.89 2404.06,2255 2460,2255 2470,2245 2635,2245 2660,2220 2800,2220 2810,2210 2840,2210 v1(2860,2230)
  Top Layer w8: v1(2860,2230) 3040,2230 3060,2210 3060,2190 3040,2170 3040,2128.5 R30.1@3068.5,2100
  Signal Layer 3 w8: v1(2860,2230) 2860,2310 2870,2320 2870,2390 3085,2605 3085,2960 3575,3450 3650,3450 J5.17@3700,3500
PB1: C27.1 J5.18 J8.1 U1.B16 U3.1 U4.6 | length 4954.5
  Top Layer w4: U1.B16@2357.48,2281.89 2358.32,2281.89 2370,2293.57 2396.43,2293.57 2410,2280
  Top Layer w6: 2410,2280 2420,2270 2465,2270 2475,2260 2640,2260 2660,2240 v1(2820,2240)
  Top Layer w8: v1(2700,2000) 2700,1910 2760,1850 2920,1850 3180,1590 3180,795 v1(3155,770) ; U4.6@3260.31,331.81 v1(3260.31,359.69)
  Top Layer w16: 3248.02,221.98 3248.94,221.06 J8.1@3248.94,162.4
  Top Layer w20: v1(3200,270) 3248.02,221.98
  Top Layer w25: U3.1@3054.13,362.6 3147.4,362.6 3147.4,322.6 v1(3200,270)
  Signal Layer 3 w8: v1(2820,2240) 2820,2310 2850,2340 2850,2400 3070,2620 3070,2970 J5.18@3600,3500
  Bottom Layer w8: v1(2700,2000) 2770,2070 2785,2070 2890,2175 2890,2245 2875,2260 2840,2260 v1(2820,2240) ; v1(3155,770) 3155,590 3240,505 3240,380 v1(3260.31,359.69)
  Bottom Layer w15: v1(3200,270) 3200,299.37 v1(3260.31,359.69)
PB2: J7.17 R11.1 SW5.3 U1.A17 | length 6863
  Top Layer w4: U1.A17@2377.17,2262.2 2399.37,2240
  Top Layer w6: 2399.37,2240 2455,2240 2475,2220 v1(2610,2220)
  Top Layer w8: v1(810,3900) 1080,3630 1405,3630 1750,3285 2195,3285 2475,3005 v1(2515,3005) ; R11.1@2130,4940 2180,4990 2760,4990 SW5.3@2900,4850
  Signal Layer 3 w8: v1(2610,2220) 2615,2220 2640,2245 2640,2330 2695,2385 2695,2450 2755,2510 2755,2755 2805,2805 2805,2935 2735,3005 v1(2515,3005) 2515,3160 v1(2630,3275)
  Bottom Layer w8: J7.17@300,3900 325,3875 350,3875 375,3850 760,3850 v1(810,3900) ; v1(2630,3275) 2655,3275 2720,3340 2720,4345 2850,4475 2850,4800 SW5.3@2900,4850
PB3: J7.15 R10.1 SW5.1 U1.B17 | length 7823.2
  Top Layer w6: v2(2339,2262) 2339.2,2262.2 U1.B17@2357.48,2262.2
  Top Layer w8: v1@1562.5,3522.5 1645,3440 1740,3440 1755,3425 1755,3390 1830,3315 2310,3315 v1(2590,3035) ; R10.1@2220,4940 2710,4940 SW5.1@2800,4850 ; v1(2710,2115) 2730,2095 2905,2095 2965,2035 v1(3005,2035)
  Signal Layer 2 w8: v1(525,4010) 525,3745 725,3545 1555,3545 v1(1570,3530) ; v1(2590,3035) 2600,3025 2875,3025 2950,2950 2950,2845 3040,2755 v1(3210,2755)
  Signal Layer 3 w8: v1(2590,3035) 2590,3200 2655,3265 v1(2655,3315) ; v1(3005,2035) 3080,2110 3100,2110 3150,2160 3150,2420 3200,2470 3200,2745 v1(3210,2755)
  Bottom Layer w6: v2(2339,2262) 2384.69,2262 2406.69,2240 2455,2240 2570,2125 2695,2125 2705,2115 v1(2710,2115)
  Bottom Layer w8: J7.15@300,4000 350,4050 485,4050 v1(525,4010) ; v1(2655,3315) 2700,3360 2700,4425 2750,4475 2750,4800 SW5.1@2800,4850
PB4: J9.31 U1.C6 | length 1896.1
  Top Layer w4: v2(2331,2517) 2326.87,2512.87 2326.87,2489.66 U1.C6@2337.8,2478.74
  Top Layer w8: v1(2480,2615) 2540,2675 2595,2675 2620,2650 2900,2650 2905,2645 3100,2645 3150,2595 3270,2595 3315,2550 3325,2550 3425,2450 v1(3495,2450)
  Bottom Layer w6: v2(2331,2517) 2356.37,2517 2375,2535.63 2405.63,2535.63 2440,2570 2440,2600.63 2454.37,2615 v1(2480,2615)
  Bottom Layer w8: v1(3495,2450) 3625,2450 3650,2425 3650,2150 J9.31@3700,2100
PB5: J1/J3.24 U1.B6 | length 3782.1
  Top Layer w4: U1.B6@2357.48,2478.74 2518.74,2478.74 2540,2500 2790,2500
  Top Layer w6: 2790,2500 2910,2380 3210,2380 3235,2405 v1(3250,2405)
  Top Layer w8: J1/J3.24@1200,1200 v1(1450,1200)
  Signal Layer 3 w8: v1(1450,1200) 1425,1225 1425,1315 1590,1480 v1(2430,1480)
  Bottom Layer w8: v1(2430,1480) 2450,1460 2565,1460 3240,2135 3240,2375 3250,2385 v1(3250,2405)
PB6: J1/J3.9 U1.F2 | length 4055.6
  Top Layer w4: U1.F2@2278.74,2557.48 2278.74,2558.74 2290,2570 2290,2600
  Top Layer w6: v1(1885,3075) 1905,3055 2015,3055 2040,3030 2245,3030 2335,2940 2335,2820 2365,2790 2365,2675 2290,2600
  Top Layer w8: v1(955,700) J1/J3.9@1100,700
  Signal Layer 3 w8: v1(955,700) 970,715 970,2115 1015,2160 v1(1015,2490)
  Bottom Layer w8: v1(1015,2490) 1230,2705 1230,2785 1520,3075 v1(1885,3075)
PB7: J1/J3.10 U1.F1 | length 4015.9
  Top Layer w4: U1.F1@2278.74,2577.17 2278.74,2608.74 2285,2615
  Top Layer w6: v1(1860,3050) 1870,3040 2010,3040 2035,3015 2195,3015 2220,2990 2220,2940 2320,2840 2320,2820 2350,2790 2350,2680 2285,2615
  Top Layer w8: v1(985,600) J1/J3.10@1100,600
  Signal Layer 3 w8: v1(985,600) 985,2105 1050,2170 v1(1050,2490)
  Bottom Layer w8: v1(1050,2490) 1245,2685 1245,2775 1530,3060 1850,3060 v1(1860,3050)
PC0: J5.26 R17.2 R20.1 R36.2 R38.2 U1.B15 | length 6385.2
  Top Layer w4: U1.B15@2357.48,2301.57 2408.43,2301.57 2415,2295
  Top Layer w6: 2415,2295 2425,2285 2470,2285 2480,2275 2655,2275 v1(2665,2265)
  Top Layer w10: R17.2@1050,5360 R36.2@1050,5231.5 1100,5181.5 1100,5130 1140,5090 1510,5090 1530,5070 v1(1770,5070) ; v1(1750,5160) R38.2@1750,5360 ; v1(1840,5100) R20.1@1910,5100 ; v1(2170,4380) 2587.31,4380 v1(2798.66,4168.66) ; v1@3160,3900 v1(3162,3900) J5.26@3600,3900
  Signal Layer 2 w10: v1(2798.66,4168.66) 2800,4170 2800,4130 3030,3900 v1(3162,3900)
  Signal Layer 3 w8: v1(2665,2265) 2665,2325 2710,2370 2710,2440 2770,2500 2770,2745 2820,2795 2820,2935 2845,2960 2900,2960 2900,3200 J5.26@3600,3900
  Bottom Layer w10: v1(1840,5100) 1825,5115 1825,5175 1810,5190 1780,5190 v1(1750,5160) 1750,5090 v1(1770,5070) 1760,5060 1760,4870 2140,4490 2140,4410 v1(2170,4380)
PC1: J5.12 R18.2 R21.1 R34.2 R35.2 U1.C15 | length 6376.6
  Top Layer w6: U1.C15@2337.8,2301.57 2337.8,2284.2 v2(2338,2284)
  Top Layer w8: v1(1800,5160) 1800,5310 R34.2@1850,5360 ; v1(2745,2130) 2765,2110 2915,2110 2955,2070 v1(2995,2070)
  Top Layer w10: R18.2@1150,5360 R35.2@1150,5231.5 1200,5181.5 1200,5130 1220,5110 1520,5110 1530,5100 v1(1800,5100) 1800,5060 1860,5000 R21.1@1910,5000 ; v1(2200,4280) 2590,4280 3530,3340 3530,3270 J5.12@3600,3200
  Signal Layer 3 w8: v1(2995,2070) 3050,2125 3090,2125 3135,2170 3135,2430 3180,2475 3180,2780 J5.12@3600,3200
  Bottom Layer w6: v2(2338,2284) 2353,2284 2365,2272 2393,2272 2410,2255 2460,2255 2575,2140 2735,2140 v1(2745,2130)
  Bottom Layer w10: v1(1800,5160) v1(1800,5100) 1800,5050 1780,5030 1780,4890 2170,4500 2170,4420 2200,4390 v1(2200,4280)
PC2: J5.15 R19.2 R22.1 R41.2 U1.D14 | length 6565.6
  Top Layer w6: v2@2298,2324.51 v2(2298,2321) 2298.26,2321.26 U1.D14@2318.11,2321.26
  Top Layer w8: v1(2805,2160) 2825,2140 2935,2140 2945,2130 2970,2130 2980,2140 2980,2175 v1(2965,2190)
  Top Layer w10: R19.2@1250,5360 1250,5170 1290,5130 v1(1550,5130) ; R41.2@1550,5360 v1(1550,5130) ; R22.1@1910,5200 1850,5200 1827.5,5177.5 1827.5,5147.5 1810,5130 v1(1550,5130) ; v1(2120,4350) 2580,4350 3480,3450 3650,3450 J5.15@3700,3400
  Signal Layer 3 w8: v1(2965,2190) 2965,2360 3050,2445 3080,2445 3120,2485 3120,2895 3575,3350 3650,3350 J5.15@3700,3400
  Bottom Layer w6: v2(2298,2321) 2354,2321 2375,2300 2405,2300 2420,2285 2470,2285 2585,2170 2795,2170 v1(2805,2160)
  Bottom Layer w10: v1(1550,5130) 1570,5130 1720,4980 1720,4830 2080,4470 2080,4390 v1(2120,4350)
PC3: J5.13 JA.13 JB.6 R37.2 R40.2 U1.C14 | length 7746.3
  Top Layer w6: v2@2318.54,2302 U1.C14@2337.8,2321.26
  Top Layer w8: v1(2775,2145) 2795,2125 2925,2125 2945,2105 v1(2975,2105)
  Top Layer w10: JA.13@900,5850 950,5800 R37.2@950,5231.5 1000,5181.5 1000,5120 1050,5070 1495,5070 1525,5040 v1(1710,5040) ; R40.2@1650,5360 1710,5300 v1(1710,5160) ; v1(1849,5132) 1867,5150 2030,5150 2090,5210 JB.6@2090,5375 ; v1(2160,4320) 2580,4320 3550,3350 3650,3350 J5.13@3700,3300
  Signal Layer 3 w8: v1(2975,2105) 3010,2140 3080,2140 3120,2180 3120,2440 3160,2480 3160,2835 3575,3250 3650,3250 J5.13@3700,3300
  Bottom Layer w6: v2(2318,2302) 2355,2302 2372,2285 2398,2285 2413,2270 2465,2270 2580,2155 2765,2155 v1(2775,2145)
  Bottom Layer w10: v1(1849,5132) 1849,5196 1830,5215 1765,5215 v1(1710,5160) v1(1710,5040) 1740,5010 1740,4850 2110,4480 2110,4400 2160,4350 v1(2160,4320)
PC4: J7.57 U1.M2 | length 2859.9
  Top Layer w4: U1.M2@2160.63,2557.48 2172.32,2569.17 2172.32,2602.31
  Top Layer w6: v1(1795,2905) 1800,2900 1910,2900 1930,2920 1970,2920 2035,2855 2035,2804 2172.32,2666.69 2172.32,2602.31
  Bottom Layer w8: J7.57@300,1900 350,1850 975,1850 1090,1965 1090,2040 1095,2045 1095,2200 1275,2380 1275,2455 1400,2580 1400,2730 1580,2910 1775,2910 1780,2905 v1(1795,2905)
PC5: J7.59 U1.M1 | length 3407.8
  Top Layer w6: v1(1770,2880) 1855,2880 1860,2885 1915,2885 1935,2905 1965,2905 2020,2850 2020,2800 2160.63,2659.37 U1.M1@2160.63,2577.17
  Signal Layer 2 w8: v1(515,1400) 515,1430 565,1480 580,1480 1115,2015 v1(1115,2030)
  Signal Layer 3 w8: J7.59@300,1800 235,1735 235,1490 275,1450 465,1450 v1(515,1400)
  Bottom Layer w8: v1(1115,2030) 1110,2035 1110,2190 1290,2370 1290,2445 1415,2570 1415,2720 1590,2895 1755,2895 v1(1770,2880)
PC6: J7.61 U1.L2 | length 3035
  Top Layer w4: U1.L2@2180.32,2557.48 2180.32,2590.17 2183.66,2593.51
  Top Layer w6: v1(1775,2935) 1780,2930 1805,2930 1820,2915 1905,2915 1925,2935 1975,2935 2050,2860 2050,2810 2070,2790 2125,2790 2141,2774 2141,2719 2183.66,2676.34 2183.66,2593.51
  Bottom Layer w8: J7.61@300,1700 250,1750 250,1925 275,1950 820,1950 1260,2390 1260,2465 1385,2590 1385,2740 1570,2925 1765,2925 v1(1775,2935)
PC7: J7.63 U1.K3 | length 3439.6
  Top Layer w4: v2@2219.8,2537.8 v2(2220,2538)
  Top Layer w6: U1.K3@2200,2537.8 v2@2219.8,2537.8
  Signal Layer 3 w8: J7.63@300,1600 350,1650 350,1725 375,1750 425,1750 500,1825 v1(500,2025) ; v1(1825,3140) 1925,3140 2065,3000 2200,3000 v1(2240,2960)
  Bottom Layer w6: v2(2220,2538) 2220,2940 v1(2240,2960)
  Bottom Layer w8: v1(500,2025) 500,2050 1115,2665 1115,2905 1130,2920 1315,2920 1480,3085 1480,3120 1500,3140 v1(1825,3140)
PD0: J2/J4.14 U1.C2 | length 3289.7
  Top Layer w4: v2@2337.8,2538.2 v2(2338,2538)
  Top Layer w6: v2@2337.8,2538.2 U1.C2@2337.8,2557.48
  Top Layer w8: v1(2415,2580) 2435,2600 2435,2630 2510,2705 2615,2705 2630,2690 2910,2690 2920,2680 3120,2680 3165,2635 3310,2635 3370,2575 3465,2480 v1(3525,2480)
  Signal Layer 2 w8: J2/J4.14@2900,900 3070,1070 3095,1070 3525,1500 3525,2190 3555,2220 3555,2250 3495,2310 3495,2415 3525,2445 v1(3525,2480)
  Bottom Layer w6: v2(2338,2538) 2361,2538 2385,2562 2397,2562 v1(2415,2580)
PD1: J2/J4.15 U1.C1 | length 2802.9
  Top Layer w6: U1.C1@2337.8,2577.17 2357.48,2596.85 2361.85,2596.85 2425,2660 2425,2840 v1(2435,2850)
  Signal Layer 2 w8: v1(2435,2850) 2436,2850 2444,2858 2742,2858 v1(2750,2850) ; v1(2650,2100) 2650,1895 v1(2670,1875)
  Signal Layer 3 w8: v1(2600,1570) 2600,1370 2628,1342 2628,1315.47 2625,1312.47 2625,1250 2670,1205 2670,1155 2775,1050 2850,1050 J2/J4.15@2900,1000 ; v1(2650,2100) 2590,2160 2590,2180 2575,2195 2575,2435 2710,2570 2710,2780 2750,2820 v1(2750,2850)
  Bottom Layer w8: v1(2600,1570) 2600,1795 2595,1800 v1(2670,1875)
PD2: J2/J4.12 U1.D2 | length 3211.2
  Top Layer w4: U1.D2@2318.11,2557.48 2306.43,2569.17 2306.43,2585 2318.28,2596.85
  Top Layer w6: 2318.28,2596.85 2341.43,2620 2345,2620 2395,2670 2395,2825 v1(2380,2840)
  Top Layer w8: v1(2650,650) 2850,650 J2/J4.12@2900,700
  Signal Layer 2 w8: v1(2380,2840) 2400,2820 2620,2820 v1(2630,2830)
  Signal Layer 3 w8: v1(2485,1545) 2485,1535 2520,1500 2520,780 v1(2650,650) ; v1(2510,2150) 2515,2155 2515,2480 2650,2615 2650,2730 2630,2750 v1(2630,2830)
  Bottom Layer w8: v1(2485,1545) 2485,1600 2535,1650 2535,1755 2510,1780 v1(2510,2150)
PD3: J1/J3.7 U1.D1 | length 4077.9
  Top Layer w6: v1(1850,3115) 1925,3115 1945,3095 2225,3095 2410,2910 2410,2665 2351.69,2606.69 2347.64,2606.69 U1.D1@2318.11,2577.17
  Top Layer w8: v1(940,900) J1/J3.7@1100,900
  Signal Layer 3 w8: v1(940,900) 955,915 955,2125 990,2160 990,2500 v1(1015,2525)
  Bottom Layer w8: v1(1015,2525) 1145,2655 1145,2865 1160,2880 1185,2880 1200,2865 1285,2865 1495,3075 1495,3110 1510,3125 1535,3125 1545,3115 v1(1850,3115)
PD4: J2/J4.36 U1.A4 | length 2882.1
  Top Layer w4: U1.A4@2377.17,2518.11 2498.11,2518.11 2510,2530 2820,2530
  Top Layer w6: 2820,2530 2890,2460 3050,2460 3057.5,2452.5 3237.5,2452.5 3310,2380 3460,2380 v1(3470,2390)
  Signal Layer 2 w8: J2/J4.36@2800,1100 2850,1150 3100,1150 3465,1515 3465,2220 3460,2225 3460,2260 3470,2270 v1(3470,2390)
PD5: J2/J4.35 U1.B4 | length 3120.6
  Top Layer w4: U1.B4@2357.48,2518.11 2369.17,2529.8 2489.8,2529.8 2500,2540 2830,2540
  Top Layer w6: 2830,2540 2890,2480 3050,2480 3060,2470 3245,2470 3305,2410 3425,2410 3440,2425 v1(3460,2425)
  Signal Layer 2 w8: J2/J4.35@2800,1000 2750,1050 2750,1125 2775,1150 2825,1150 2850,1175 2850,1225 2875,1250 3175,1250 3445,1520 3445,2215 3440,2220 3440,2405 v1(3460,2425)
PD6: J5.38 JP4.2 U1.B3 | length 4195.7
  Top Layer w4: U1.B3@2357.48,2537.8 2482.8,2537.8 2495,2550 2840,2550
  Top Layer w6: 2840,2550 2895,2495 v1(3070,2495)
  Signal Layer 2 w8: v1(3070,2495) 3230,2495 3300,2425 3330,2425 3395,2490 3470,2490 v1(3500,2520)
  Signal Layer 3 w8: v1(3490,4410) 3510,4410 J5.38@3600,4500
  Bottom Layer w8: JP4.2@2600,2000 2650,1950 2840,1950 2930,2040 2930,2380 3045,2495 v1(3070,2495) ; v1(3490,4410) 3490,2645 3500,2635 v1(3500,2520)
PD7: J5.3 JP5.1 U1.B2 | length 2199.5
  Top Layer w4: U1.B2@2357.48,2557.48 2369.17,2545.8 2475.8,2545.8 2490,2560 2850,2560
  Top Layer w6: 2850,2560 2900,2510 3035,2510 v1(3045,2520)
  Signal Layer 2 w8: v1(3045,2520) 3270,2520 3290,2500 3320,2500 3340,2520 v1(3460,2520)
  Signal Layer 3 w8: v1(3460,2520) 3550,2610 3550,2725 3575,2750 3650,2750 J5.3@3700,2800
  Bottom Layer w8: JP5.1@2800,2000 2910,2110 2910,2385 v1(3045,2520)
PE0: J1/J3.28 U1.H3 | length 3287.4
  Top Layer w6: U1.H3@2239.37,2537.8 v2@2258.8,2537.8
  Signal Layer 2 w8: v1(1330,2615) 1370,2615 1560,2805 1675,2805 1755,2725 v1(1815,2725)
  Signal Layer 3 w8: v1(1300,855) 1350,855 1380,885 1380,915 1370,925 1370,1125 1345,1150 1345,2085 1305,2125 1305,2175 1250,2230 1250,2535 v1(1330,2615) ; v1(1815,2725) 1830,2740 2235,2740 v1(2260,2715)
  Bottom Layer w6: v2(2259,2538) 2260,2539 v1(2260,2715)
  Bottom Layer w8: J1/J3.28@1200,800 1245,800 v1(1300,855)
PE1: J1/J3.2 U1.H2 | length 3096.8
  Top Layer w4: U1.H2@2239.37,2557.48 2239.37,2720.9
  Top Layer w6: v1(1800,3020) 1810,3010 2000,3010 2030,2980 2140,2980 2155,2965 2155,2945 2205,2895 2205,2755.27 2239.37,2720.9
  Top Layer w8: v1(1010,1400) J1/J3.2@1100,1400
  Signal Layer 3 w8: v1(1010,1400) 1010,1430 1000,1440 1000,1675 1205,1880 1205,1935 1190,1950 1190,2050 1125,2115 1125,2485 v1(1120,2490)
  Bottom Layer w8: v1(1120,2490) 1275,2645 1275,2755 1550,3030 1790,3030 v1(1800,3020)
PE2: J2/J4.32 U1.G1 | length 3098.6
  Top Layer w4: U1.G1@2259.06,2577.17 2259.06,2584.06 2270,2595 2270,2620
  Top Layer w6: 2270,2620 2335,2685 2335,2730 2290,2775 v1(2290,2820)
  Top Layer w8: v1(2650,700) J2/J4.32@2800,700
  Signal Layer 2 w8: v1(2290,2820) 2305,2805 2655,2805 v1(2665,2815)
  Signal Layer 3 w8: v1(2520,1535) 2540,1515 2540,810 v1(2650,700) ; v1(2540,2125) 2540,2155 2530,2165 2530,2465 2665,2600 v1(2665,2815)
  Bottom Layer w8: v1(2520,1535) 2520,1542.53 2505,1557.53 2505,1600 2550,1645 2550,1765 2525,1790 2525,2110 v1(2540,2125)
PE3: J2/J4.31 U1.G2 | length 4941.6
  Top Layer w4: 2255,2610 2247.37,2602.37 2247.37,2570 2259.06,2558.31 U1.G2@2259.06,2557.48
  Top Layer w6: v1(1830,3035) 1835,3035 1845,3025 2005,3025 2030,3000 2190,3000 2205,2985 2205,2915 2220,2900 2220,2823.62 2320,2723.62 2320,2685 2255,2620 2255,2610
  Signal Layer 2 w8: v1(1180,1895) 1380,1895 1670,1605 1950,1605 2010,1545 2105,1545 2350,1300 2440,1300 2750,990 2750,650 J2/J4.31@2800,600
  Signal Layer 3 w8: v1(1085,2490) 1100,2475 1100,2060 1090,2050 1090,2020 1180,1930 v1(1180,1895)
  Bottom Layer w8: v1(1085,2490) 1260,2665 1260,2765 1540,3045 1820,3045 v1(1830,3035)
PE4: J1/J3.6 U1.A5 | length 3998.9
  Top Layer w4: U1.A5@2377.17,2498.43 2498.43,2498.43 2520,2520 2810,2520
  Top Layer w6: 2810,2520 2905,2425 v1(3190,2425)
  Top Layer w8: J1/J3.6@1100,1000 1150,950 1265,950 1315,1000 v1(1410,1000)
  Signal Layer 3 w8: v1(1410,1000) 1410,1375 1565,1530 v1(2430,1530)
  Bottom Layer w8: v1(2430,1530) 2465,1530 2490,1505 2570,1505 3190,2125 v1(3190,2425)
